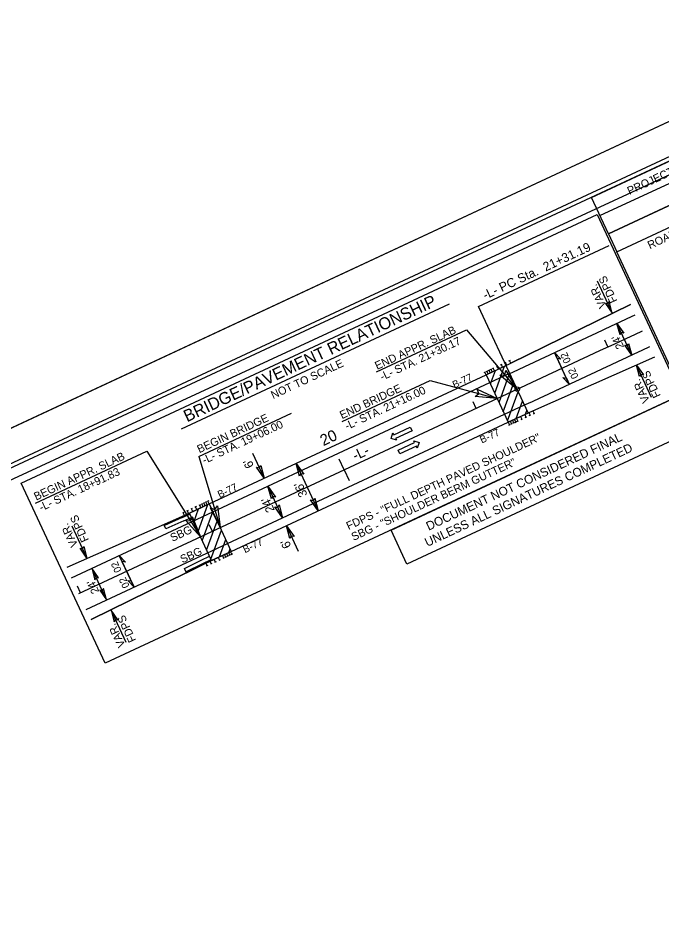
# Model space of a CAD drawing. Extents: x 2320593 to 2322597, y 921119 to 922832.
# Drawn here: x 2321588 to 2321991, y 922260 to 922823 of the extents above; entities that cross this region are included whole.
import ezdxf

# ---------------------------------------------------------------- set-up
doc = ezdxf.new("R2010")
doc.units = 0
for name, color, linetype in [('Matchline Text', 7, 'Continuous'), ('Prop Approach Slab', 7, 'Continuous'), ('Prop Conc Shoulder Berm Gutter', 7, 'Continuous'), ('Prop Dimension', 7, 'Continuous'), ('Prop DSN Text', 7, 'Continuous'), ('Prop EOT', 7, 'Continuous'), ('Prop Guardrail', 7, 'Continuous'), ('Prop Guardrail Anchor Unit CELL', 7, 'Continuous'), ('Prop Horizontal Alignment', 7, 'Continuous'), ('Prop Horizontal Alignment Station Label', 7, 'Continuous'), ('Prop Horizontal Alignment Tick Label', 7, 'Continuous'), ('Prop Horizontal Alignment Tick Large', 7, 'Continuous'), ('Prop Horizontal Alignment Tick Small', 7, 'Continuous'), ('Prop Lane Arrow CELL', 7, 'Continuous'), ('Prop Leader Line Medium', 7, 'Continuous'), ('Prop Paved Shoulder', 7, 'Continuous'), ('Prop Roadway Bridge', 7, 'Continuous'), ('Prop Structure Anchor Unit CELL', 7, 'Continuous'), ('Prop Superelevation  Arrow CELL', 7, 'Continuous'), ('Prop Superelevation Label', 7, 'Continuous'), ('Prop Terminator CELL', 7, 'Continuous'), ('Sheet Cutting Line CELL', 7, 'Continuous'), ('Sheet Layout Plan Border', 7, 'Continuous'), ('Sheet Plan And Profile CELL', 7, 'Continuous'), ('Sheet Plot Border Inside CELL', 7, 'Continuous'), ('Sheet Plot Border Outside CELL', 7, 'Continuous'), ('Sheet Sticker Exception Certification CELL', 7, 'Continuous')]:
    doc.layers.add(name, color=color, linetype=linetype)

# ---------------------------------------------------------------- blocks, each defined once
blk = doc.blocks.new('STICKER EXCEPTION CERTIFICATION')
at = {"layer": 'Sheet Sticker Exception Certification CELL'}
for p, q in [((0, -0.47), (0, 0)), ((0, 0), (4.001, 0)), ((4.001, 0), (4.001, -0.47)), ((4.001, -0.47), (0, -0.47))]:
    blk.add_line(p, q, dxfattribs=at)
for s, p in [('DOCUMENT NOT CONSIDERED FINAL', (0.421, -0.207)), ('UNLESS ALL SIGNATURES COMPLETED', (0.32, -0.383))]:
    blk.add_text(s, height=0.11, dxfattribs=at).set_placement(p)

msp = doc.modelspace()

# ---------------------------------------------------------------- linework, layer by layer
at = {"layer": 'Matchline Text'}
for p, q in [((2321883.72, 922594.01), (2321886.8, 922602.46)), ((2321886.41, 922588.24), (2321892.56, 922605.15)), ((2321889.09, 922582.47), (2321895.69, 922600.59)), ((2321891.78, 922576.7), (2321898.38, 922594.83)), ((2321894.47, 922570.93), (2321901.07, 922589.06)), ((2321899.8, 922572.41), (2321903.76, 922583.29)), ((2321905.57, 922575.1), (2321906.45, 922577.52)), ((2321700.97, 922501.8), (2321707.13, 922518.72)), ((2321698.28, 922507.57), (2321701.36, 922516.03)), ((2321703.66, 922496.04), (2321710.26, 922514.16)), ((2321706.35, 922490.27), (2321712.95, 922508.39)), ((2321709.04, 922484.5), (2321715.64, 922502.62)), ((2321714.37, 922485.97), (2321718.33, 922496.86)), ((2321720.13, 922488.66), (2321721.02, 922491.09))]:
    msp.add_line(p, q, dxfattribs=at)
at = {"layer": 'Prop Approach Slab'}
for p, q in [((2321881.03, 922599.77), (2321893.39, 922605.54)), ((2321893.39, 922605.54), (2321907.22, 922575.87)), ((2321907.22, 922575.87), (2321894.86, 922570.1)), ((2321695.6, 922513.34), (2321707.96, 922519.1)), ((2321709.43, 922483.67), (2321695.6, 922513.34)), ((2321721.79, 922489.43), (2321709.43, 922483.67))]:
    msp.add_line(p, q, dxfattribs=at)
at = {"layer": 'Prop Conc Shoulder Berm Gutter'}
for p, q in [((2321690.87, 922511.14), (2321695.6, 922513.34)), ((2321691.15, 922510.53), (2321695.88, 922512.74)), ((2321679.67, 922506.19), (2321690.87, 922511.14)), ((2321691.15, 922510.53), (2321679.95, 922505.58)), ((2321703.9, 922481.83), (2321709.14, 922484.27)), ((2321693.42, 922476.69), (2321703.9, 922481.83)), ((2321693.72, 922476.05), (2321705.86, 922482.01)), ((2321705.86, 922482.01), (2321709.43, 922483.67))]:
    msp.add_line(p, q, dxfattribs=at)
at = {"layer": 'Prop Dimension'}
for p, q in [((2321950.48, 922658.45), (2321959.85, 922638.3)), ((2321972.05, 922612.11), (2321962.81, 922631.89)), ((2321812.45, 922601.57), (2321868.86, 922627.86)), ((2321868.86, 922627.86), (2321900.3, 922590.7)), ((2321984.45, 922585.58), (2321975.04, 922605.71)), ((2321791.05, 922570.54), (2321846.09, 922596.2)), ((2321846.09, 922596.2), (2321887.94, 922584.94)), ((2321701.54, 922548.76), (2321759.46, 922575.75)), ((2321599.46, 922519.62), (2321669.07, 922552.06)), ((2321669.07, 922552.06), (2321702.51, 922498.51)), ((2321701.54, 922548.76), (2321714.87, 922504.27)), ((2321622.12, 922505.39), (2321631.53, 922485.26)), ((2321643.74, 922459.08), (2321634.54, 922478.87)), ((2321656.09, 922432.52), (2321646.72, 922452.67))]:
    msp.add_line(p, q, dxfattribs=at)
at = {"layer": 'Prop DSN Text'}
for p, q in [((2321735, 922550.83), (2321742.33, 922535.12)), ((2321762.26, 922544.41), (2321776.1, 922514.75)), ((2321744.64, 922530.18), (2321753.87, 922510.4)), ((2321756.17, 922505.46), (2321763.6, 922489.55))]:
    msp.add_line(p, q, dxfattribs=at)
at = {"layer": 'Prop EOT'}
for p, q in [((2321621.89, 922472.97), (2321895.85, 922600.67)), ((2321631.11, 922453.19), (2321905.07, 922580.89))]:
    msp.add_line(p, q, dxfattribs=at)
for radius, end in [(363699.09, 295.0049126), (363720.91, 295.0049118)]:
    msp.add_arc((2168240.04, 1252247.32), radius, 294.9912984, end, dxfattribs=at)
at = {"layer": 'Prop Guardrail'}
for p, q in [((2321971.17, 922643.63), (2321896.48, 922606.98)), ((2321910.31, 922577.31), (2321986.41, 922610.94)), ((2321692.51, 922511.9), (2321618.91, 922479.37)), ((2321634.09, 922446.79), (2321705.86, 922482.01))]:
    msp.add_line(p, q, dxfattribs=at)
at = {"layer": 'Prop Horizontal Alignment'}
msp.add_line((2321626.5, 922463.08), (2321900.46, 922590.78), dxfattribs=at)
msp.add_arc((2168240.04, 1252247.32), 363710, 294.9912984, 295.0049122, dxfattribs=at)
at = {"layer": 'Prop Horizontal Alignment Station Label'}
for p, q in [((2321876.34, 922642.53), (2321957.94, 922680.57)), ((2321899.89, 922592.01), (2321876.34, 922642.53))]:
    msp.add_line(p, q, dxfattribs=at)
msp.add_circle((2321900.46, 922590.78), 1.36, dxfattribs=at)
at = {"layer": 'Prop Horizontal Alignment Tick Large'}
for q in [(2321789.27, 922546.97), (2321795.42, 922533.78)]:
    msp.add_line((2321792.34, 922540.38), q, dxfattribs=at)
at = {"layer": 'Prop Horizontal Alignment Tick Small'}
for p, q in [((2321957.17, 922617.21), (2321955.25, 922621.33)), ((2321874.76, 922578.79), (2321872.84, 922582.91)), ((2321709.93, 922501.96), (2321708.01, 922506.08)), ((2321627.51, 922463.55), (2321625.59, 922467.67))]:
    msp.add_line(p, q, dxfattribs=at)
at = {"layer": 'Prop Lane Arrow CELL'}
for p, q in [((2321821.62, 922560), (2321822.83, 922563.42)), ((2321822.83, 922563.42), (2321823.34, 922562.33)), ((2321823.34, 922562.33), (2321833.6, 922567.11)), ((2321834.73, 922564.69), (2321824.47, 922559.91)), ((2321833.6, 922567.11), (2321834.73, 922564.69)), ((2321824.98, 922558.81), (2321821.62, 922560)), ((2321824.47, 922559.91), (2321824.98, 922558.81)), ((2321826.08, 922552.71), (2321836.33, 922557.49)), ((2321836.33, 922557.49), (2321835.82, 922558.59)), ((2321835.82, 922558.59), (2321839.19, 922557.4)), ((2321839.19, 922557.4), (2321837.97, 922553.98)), ((2321827.2, 922550.3), (2321826.08, 922552.71)), ((2321837.46, 922555.08), (2321827.2, 922550.3)), ((2321837.97, 922553.98), (2321837.46, 922555.08))]:
    msp.add_line(p, q, dxfattribs=at)
at = {"layer": 'Prop Leader Line Medium'}
msp.add_line((2321690.67, 922566.07), (2321858.23, 922644.17), dxfattribs=at)
msp.add_lwpolyline([(2321590.4, 922532.13), (2321950.44, 922699.95), (2322002.96, 922587.28), (2321642.92, 922419.46)], close=True, dxfattribs=at)
at = {"layer": 'Prop Paved Shoulder'}
for p, q in [((2321896.48, 922606.98), (2321971.17, 922643.63)), ((2321910.31, 922577.31), (2321986.41, 922610.94)), ((2321881.03, 922599.77), (2321896.48, 922606.98)), ((2321894.86, 922570.1), (2321910.31, 922577.31)), ((2321692.51, 922511.9), (2321707.96, 922519.1)), ((2321692.51, 922511.9), (2321618.91, 922479.37)), ((2321692.11, 922508.41), (2321680.94, 922503.47)), ((2321692.11, 922508.41), (2321696.86, 922510.62)), ((2321680.94, 922503.47), (2321679.67, 922506.19)), ((2321702.89, 922483.93), (2321708.16, 922486.39)), ((2321705.86, 922482.01), (2321721.79, 922489.43)), ((2321705.86, 922482.01), (2321634.09, 922446.79)), ((2321692.43, 922478.8), (2321702.89, 922483.93)), ((2321693.71, 922476.05), (2321692.43, 922478.8))]:
    msp.add_line(p, q, dxfattribs=at)
at = {"layer": 'Prop Roadway Bridge'}
for p, q in [((2321707.96, 922519.1), (2321881.03, 922599.77)), ((2321881.03, 922599.77), (2321894.86, 922570.1)), ((2321721.79, 922489.43), (2321894.86, 922570.1)), ((2321707.96, 922519.1), (2321721.79, 922489.43))]:
    msp.add_line(p, q, dxfattribs=at)
at = {"layer": 'Prop Structure Anchor Unit CELL'}
for p, q in [((2321895.24, 922608.4), (2321896.18, 922608.84)), ((2321896.48, 922606.98), (2321895.71, 922608.62)), ((2321881.03, 922599.77), (2321896.48, 922606.98)), ((2321882.36, 922602.4), (2321883.31, 922602.84)), ((2321883.6, 922600.97), (2321882.84, 922602.62)), ((2321883.65, 922603), (2321884.6, 922603.44)), ((2321884.89, 922601.57), (2321884.12, 922603.22)), ((2321884.94, 922603.6), (2321885.88, 922604.04)), ((2321886.18, 922602.17), (2321885.41, 922603.82)), ((2321887.51, 922604.8), (2321888.46, 922605.24)), ((2321888.75, 922603.38), (2321887.99, 922605.02)), ((2321890.09, 922606), (2321891.03, 922606.44)), ((2321891.33, 922604.58), (2321890.56, 922606.22)), ((2321892.66, 922607.2), (2321893.61, 922607.64)), ((2321893.91, 922605.78), (2321893.14, 922607.42)), ((2321879.79, 922601.2), (2321880.73, 922601.64)), ((2321881.03, 922599.77), (2321880.26, 922601.42)), ((2321881.08, 922601.8), (2321882.02, 922602.24)), ((2321882.32, 922600.37), (2321881.55, 922602.02)), ((2321894.86, 922570.1), (2321910.31, 922577.31)), ((2321905.16, 922574.91), (2321905.93, 922573.26)), ((2321907.73, 922576.11), (2321908.5, 922574.46)), ((2321908.03, 922574.24), (2321908.98, 922574.68)), ((2321910.31, 922577.31), (2321911.08, 922575.66)), ((2321910.61, 922575.44), (2321911.55, 922575.88)), ((2321894.86, 922570.1), (2321895.63, 922568.46)), ((2321895.15, 922568.24), (2321896.1, 922568.68)), ((2321896.15, 922570.7), (2321896.91, 922569.06)), ((2321896.44, 922568.84), (2321897.39, 922569.28)), ((2321897.43, 922571.31), (2321898.2, 922569.66)), ((2321897.73, 922569.44), (2321898.67, 922569.88)), ((2321898.72, 922571.91), (2321899.49, 922570.26)), ((2321899.02, 922570.04), (2321899.96, 922570.48)), ((2321900.01, 922572.51), (2321900.78, 922570.86)), ((2321900.3, 922570.64), (2321901.25, 922571.08)), ((2321902.58, 922573.71), (2321903.35, 922572.06)), ((2321902.88, 922571.84), (2321903.82, 922572.28)), ((2321905.46, 922573.04), (2321906.4, 922573.48)), ((2321707.96, 922519.1), (2321692.51, 922511.9)), ((2321702.51, 922518.57), (2321701.57, 922518.13)), ((2321702.81, 922516.7), (2321702.04, 922518.35)), ((2321703.8, 922519.17), (2321702.85, 922518.73)), ((2321704.1, 922517.3), (2321703.33, 922518.95)), ((2321705.09, 922519.77), (2321704.14, 922519.33)), ((2321705.38, 922517.9), (2321704.61, 922519.55)), ((2321706.37, 922520.37), (2321705.43, 922519.93)), ((2321706.67, 922518.5), (2321705.9, 922520.15)), ((2321707.66, 922520.97), (2321706.72, 922520.53)), ((2321707.96, 922519.1), (2321707.19, 922520.75)), ((2321692.21, 922513.77), (2321691.27, 922513.33)), ((2321692.51, 922511.9), (2321691.74, 922513.55)), ((2321694.78, 922514.97), (2321693.84, 922514.53)), ((2321695.08, 922513.1), (2321694.31, 922514.75)), ((2321697.36, 922516.17), (2321696.42, 922515.73)), ((2321697.66, 922514.3), (2321696.89, 922515.95)), ((2321699.94, 922517.37), (2321698.99, 922516.93)), ((2321700.23, 922515.5), (2321699.46, 922517.15)), ((2321721.32, 922489.21), (2321705.86, 922482.01)), ((2321711.01, 922484.41), (2321711.78, 922482.76)), ((2321713.59, 922485.61), (2321714.36, 922483.96)), ((2321714.83, 922484.18), (2321713.89, 922483.74)), ((2321716.17, 922486.81), (2321716.93, 922485.16)), ((2321717.41, 922485.38), (2321716.46, 922484.94)), ((2321717.45, 922487.41), (2321718.22, 922485.76)), ((2321718.69, 922485.98), (2321717.75, 922485.54)), ((2321718.74, 922488.01), (2321719.51, 922486.36)), ((2321719.98, 922486.58), (2321719.04, 922486.14)), ((2321720.03, 922488.61), (2321720.8, 922486.96)), ((2321721.27, 922487.18), (2321720.33, 922486.74)), ((2321721.32, 922489.21), (2321722.08, 922487.56)), ((2321722.56, 922487.78), (2321721.61, 922487.34)), ((2321705.86, 922482.01), (2321706.63, 922480.36)), ((2321707.1, 922480.58), (2321706.16, 922480.14)), ((2321708.44, 922483.21), (2321709.21, 922481.56)), ((2321709.68, 922481.78), (2321708.74, 922481.34)), ((2321712.26, 922482.98), (2321711.31, 922482.54))]:
    msp.add_line(p, q, dxfattribs=at)
at = {"layer": 'Prop Superelevation  Arrow CELL'}
for p, q in [((2321923.71, 922613.65), (2321928.33, 922603.76)), ((2321932.98, 922593.89), (2321923.75, 922613.67)), ((2321932.98, 922593.89), (2321928.36, 922603.78)), ((2321651.74, 922486.88), (2321656.36, 922476.99)), ((2321661.01, 922467.12), (2321651.78, 922486.9)), ((2321661.01, 922467.12), (2321656.4, 922477.01))]:
    msp.add_line(p, q, dxfattribs=at)
for points in [[(2321923.71, 922613.65), (2321927.67, 922609.48), (2321925.49, 922609.84)], [(2321932.98, 922593.89), (2321929.02, 922598.07), (2321931.2, 922597.7)], [(2321651.74, 922486.88), (2321655.7, 922482.71), (2321653.52, 922483.07)], [(2321661.01, 922467.12), (2321657.06, 922471.3), (2321659.23, 922470.93)]]:
    msp.add_lwpolyline(points, close=True, dxfattribs=at)
at = {"layer": 'Prop Terminator CELL'}
for points in [[(2321955.65, 922644.37), (2321959.85, 922638.3), (2321957.94, 922645.48), (2321957.16, 922644.09)], [(2321964.75, 922624.76), (2321962.81, 922631.89), (2321967.08, 922625.81), (2321965.51, 922626.1)], [(2321970.1, 922619.24), (2321972.05, 922612.11), (2321967.78, 922618.19), (2321969.35, 922617.9)], [(2321893.36, 922602.51), (2321900.3, 922590.7), (2321889.7, 922599.51), (2321892.65, 922599.75)], [(2321976.99, 922598.59), (2321975.04, 922605.71), (2321979.31, 922599.63), (2321977.75, 922599.92)], [(2321875.51, 922590.69), (2321887.94, 922584.94), (2321874.21, 922586.15), (2321876.5, 922588.02)], [(2321740.15, 922543.13), (2321742.33, 922535.12), (2321737.53, 922541.96), (2321739.29, 922541.63)], [(2321764.44, 922536.4), (2321762.26, 922544.41), (2321767.06, 922537.57), (2321765.29, 922537.9)], [(2321746.82, 922522.17), (2321744.64, 922530.18), (2321749.43, 922523.34), (2321747.67, 922523.67)], [(2321751.68, 922518.42), (2321753.87, 922510.4), (2321749.07, 922517.25), (2321750.83, 922516.91)], [(2321773.92, 922522.76), (2321776.1, 922514.75), (2321771.3, 922521.59), (2321773.06, 922521.26)], [(2321713.23, 922517.87), (2321714.87, 922504.27), (2321708.68, 922516.58), (2321711.47, 922515.62)], [(2321697.33, 922511.19), (2321702.51, 922498.51), (2321693.29, 922508.75), (2321696.23, 922508.56)], [(2321758.36, 922497.45), (2321756.17, 922505.46), (2321760.97, 922498.62), (2321759.21, 922498.95)], [(2321629.58, 922492.38), (2321631.53, 922485.26), (2321627.26, 922491.34), (2321628.82, 922491.05)], [(2321638.74, 922472.8), (2321634.54, 922478.87), (2321636.45, 922471.69), (2321637.23, 922473.08)], [(2321639.53, 922465.15), (2321643.74, 922459.08), (2321641.83, 922466.26), (2321641.05, 922464.87)], [(2321650.92, 922446.6), (2321646.72, 922452.67), (2321648.63, 922445.49), (2321649.41, 922446.88)]]:
    msp.add_lwpolyline(points, close=True, dxfattribs=at)
at = {"layer": 'Sheet Cutting Line CELL'}
msp.add_line((2322134.06, 922822.69), (2320608.18, 922111.45), dxfattribs=at)
at = {"layer": 'Sheet Layout Plan Border'}
msp.add_lwpolyline([(2322313.35, 922279.99), (2321040.83, 921692.7), (2320815.91, 922178.3), (2322085.86, 922766.57)], close=True, dxfattribs=at)
at = {"layer": 'Sheet Plan And Profile CELL'}
for p, q in [((2321952.14, 922699.22), (2322133.46, 922783.74)), ((2321957.42, 922687.9), (2322138.74, 922772.41)), ((2321957.42, 922687.9), (2321962.7, 922676.57))]:
    msp.add_line(p, q, dxfattribs=at)
for points in [[(2322128.15, 922795.12), (2320768.59, 922161.4), (2321212.2, 921209.71), (2322571.76, 921843.43)], [(2321946.83, 922710.6), (2322128.15, 922795.12), (2322138.74, 922772.41), (2321957.42, 922687.9)], [(2321962.7, 922676.57), (2322053.38, 922718.83), (2322100.91, 922616.87), (2322010.23, 922574.6)]]:
    msp.add_lwpolyline(points, close=True, dxfattribs=at)
at = {"layer": 'Sheet Plot Border Inside CELL'}
msp.add_lwpolyline([(2321074.13, 921142.59), (2322584.14, 921846.44), (2322138.43, 922802.66), (2320628.41, 922098.81)], close=True, dxfattribs=at)
at = {"layer": 'Sheet Plot Border Outside CELL'}
msp.add_lwpolyline([(2321070.79, 921118.97), (2322596.67, 921830.22), (2322134.06, 922822.69), (2320608.18, 922111.45)], close=True, dxfattribs=at)

# ---------------------------------------------------------------- block references
at = {"layer": 'Sheet Cutting Line CELL', "xscale": 49.99999999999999, "yscale": 50, "rotation": 24.991298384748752}
msp.add_blockref('STICKER EXCEPTION CERTIFICATION', (2321821.65, 922502.77), dxfattribs=at)

# ---------------------------------------------------------------- texts
at = {"layer": 'Prop DSN Text'}
for s, height, rotation, p in [('FDPS', 5, 114.9349, (2321963.19, 922645.94)), ('VAR.', 5, 114.9349, (2321956.39, 922642.78)), ('BRIDGE/PAVEMENT RELATIONSHIP', 7.5, 25.0477, (2321694.11, 922570.04)), ("24'", 5, 115.0477, (2321967.39, 922617.18)), ('VAR.', 5, 115.0477, (2321983.46, 922583.51)), ('FDPS', 5, 115.0477, (2321990.26, 922586.69)), ("6'", 5.456, 115.7165, (2321736.09, 922542.86)), ("36'", 5.456, 114.3416, (2321769.54, 922524.73)), ("24'", 5.456, 114.3416, (2321749.01, 922515.16)), ('VAR.', 5, 115.0477, (2321626.09, 922493.38)), ('FDPS', 5, 115.0477, (2321632.88, 922496.56)), ("6'", 5.456, 115.7165, (2321759.41, 922492.71)), ("24'", 5, 114.9349, (2321639.36, 922464.27)), ('FDPS', 5, 114.9349, (2321662.45, 922433.91)), ('VAR.', 5, 114.9349, (2321655.65, 922430.74))]:
    msp.add_text(s, height=height, rotation=rotation, dxfattribs=at).set_placement(p)
at = {"layer": 'Prop Guardrail Anchor Unit CELL'}
for p in [(2321861.25, 922591.18), (2321878.35, 922556.78), (2321714.49, 922522.62), (2321730.3, 922488.24)]:
    msp.add_text('B-77', height=4.546, rotation=25.0187, dxfattribs=at).set_placement(p)
at = {"layer": 'Prop Horizontal Alignment Station Label'}
for s, height, rotation, p in [('-L- PC Sta.  21+31.19', 5.6577, 24.9913, (2321880.51, 922646.63)), ('-L-', 6.365, 25.0187, (2321799.24, 922545.99))]:
    msp.add_text(s, height=height, rotation=rotation, dxfattribs=at).set_placement(p)
at = {"layer": 'Prop Horizontal Alignment Tick Label'}
msp.add_text('20', height=7, rotation=24.9913, dxfattribs=at).set_placement((2321779.25, 922555.11))
at = {"layer": 'Prop Leader Line Medium'}
for s, p in [('END APPR. SLAB', (2321812.9, 922602.81)), ('-L- STA. 21+30.17', (2321816.07, 922596.01)), ('NOT TO SCALE', (2321747.94, 922584.5)), ('END BRIDGE', (2321790.94, 922572)), ('-L- STA. 21+16.00', (2321794.11, 922565.2)), ('BEGIN BRIDGE', (2321701.81, 922550.7)), ('-L- STA. 19+06.00', (2321704.98, 922543.9)), ('FDPS - "FULL DEPTH PAVED SHOULDER"', (2321795.05, 922502.72)), ('BEGIN APPR. SLAB', (2321599.84, 922521.12)), ('SBG - "SHOULDER BERM GUTTER"', (2321798.22, 922495.92)), ('-L- STA. 18+91.83', (2321603, 922514.32)), ('SBG', (2321685, 922495.32)), ('SBG', (2321691.26, 922481.89))]:
    msp.add_text(s, height=5, rotation=24.9913, dxfattribs=at).set_placement(p)
at = {"layer": 'Prop Superelevation Label'}
for p in [(2321934.19, 922608.17), (2321938.95, 922598.5), (2321653.33, 922477.42), (2321658.32, 922467.69)]:
    msp.add_text('02', height=4.546, rotation=115.0187, dxfattribs=at).set_placement(p)
at = {"layer": 'Sheet Plan And Profile CELL'}
for s, p in [('PROJECT REFERENCE NO.', (2321970.63, 922712.09)), ('ROADWAY DESIGN', (2321983.37, 922678.15))]:
    msp.add_text(s, height=5.0001, rotation=24.9913, dxfattribs=at).set_placement(p)

doc.saveas('drawing.dxf')
